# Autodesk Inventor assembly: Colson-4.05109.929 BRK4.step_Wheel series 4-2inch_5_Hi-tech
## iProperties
Created: 2010-10
Part Number: Colson-4.05109.929 BRK4.step_Wheel series 4-2inch_5_Hi-tech
Document SubType Name: Assembly
Designer: Administrator
Author: Administrator
